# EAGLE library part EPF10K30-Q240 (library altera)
EPF10K30 FLEX 10K family
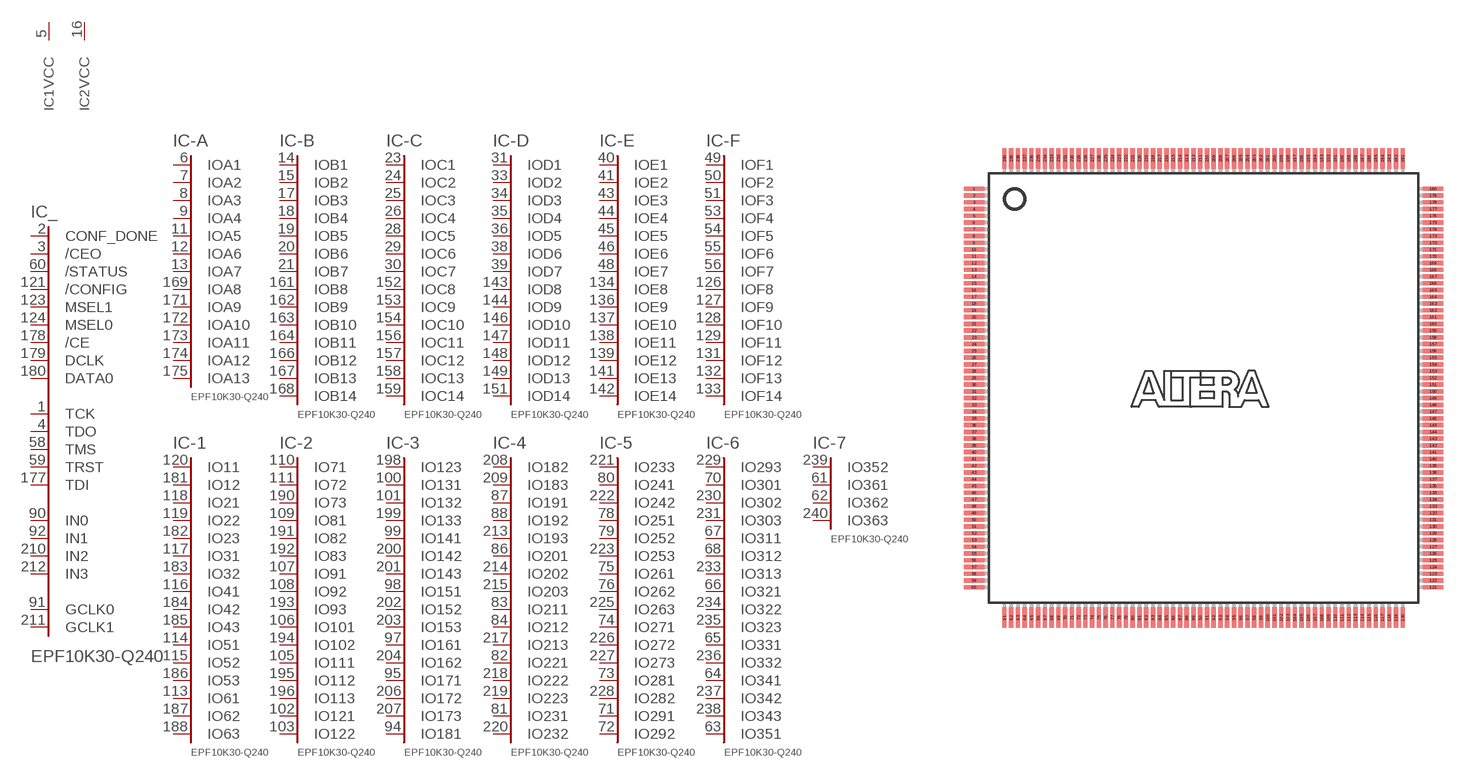
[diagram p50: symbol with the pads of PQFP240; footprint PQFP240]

Designator prefix IC; gates _=100R240C -A=A13 -B=B14 -C=C14 -D=D14 -E=E14 -F=F14 -1=63-K30Q -2=122-K30Q -3=181-K30Q -4=232-K30Q -5=292-K30Q -6=351-K30Q -7=363-K30Q 1=VCCINT 2=VCCINT 3=VCCINT 4=VCCINT 5=VCCINT 6=VCCINT 7=VCCINT 8=VCCINT 9=VCCINT 10=VCCINT 11=VCCINT 12=VCCINT 13=VCCINT 14=VCCINT 15=VCCINT 16=VCCINT 17=VCCINT 18=VCCINT 19=VCCINT 20=GNDINT 21=GNDINT 22=GNDINT 23=GNDINT 24=GNDINT 25=GNDINT 26=GNDINT 27=GNDINT 28=GNDINT 29=GNDINT 30=GNDINT 31=GNDINT 32=GNDINT 33=GNDINT 34=GNDINT 35=GNDINT 36=GNDINT 37=GNDINT

## EPF10K30-Q240 (MPN: EPF10K30AQC240-3N; OC_FARNELL: 1549384; OC_NEWARK: 51R8956)  [PQFP240]
1  _:TCK
2  _:CONF_DONE  in
3  _:/CEO  in
4  _:TDO
5  1:VCC  pwr
6  -A:IOA1
7  -A:IOA2
8  -A:IOA3
9  -A:IOA4
10  20:GND  pwr
11  -A:IOA5
12  -A:IOA6
13  -A:IOA7
14  -B:IOB1
15  -B:IOB2
16  2:VCC  pwr
17  -B:IOB3
18  -B:IOB4
19  -B:IOB5
20  -B:IOB6
21  -B:IOB7
22  21:GND  pwr
23  -C:IOC1
24  -C:IOC2
25  -C:IOC3
26  -C:IOC4
27  3:VCC  pwr
28  -C:IOC5
29  -C:IOC6
30  -C:IOC7
31  -D:IOD1
32  22:GND  pwr
33  -D:IOD2
34  -D:IOD3
35  -D:IOD4
36  -D:IOD5
37  4:VCC  pwr
38  -D:IOD6
39  -D:IOD7
40  -E:IOE1
41  -E:IOE2
42  23:GND  pwr
43  -E:IOE3
44  -E:IOE4
45  -E:IOE5
46  -E:IOE6
47  5:VCC  pwr
48  -E:IOE7
49  -F:IOF1
50  -F:IOF2
51  -F:IOF3
52  24:GND  pwr
53  -F:IOF4
54  -F:IOF5
55  -F:IOF6
56  -F:IOF7
57  6:VCC  pwr
58  _:TMS
59  _:TRST
60  _:/STATUS  in
61  -7:IO361
62  -7:IO362
63  -6:IO351
64  -6:IO341
65  -6:IO331
66  -6:IO321
67  -6:IO311
68  -6:IO312
69  25:GND  pwr
70  -6:IO301
71  -5:IO291
72  -5:IO292
73  -5:IO281
74  -5:IO271
75  -5:IO261
76  -5:IO262
77  7:VCC  pwr
78  -5:IO251
79  -5:IO252
80  -5:IO241
81  -4:IO231
82  -4:IO221
83  -4:IO211
84  -4:IO212
85  26:GND  pwr
86  -4:IO201
87  -4:IO191
88  -4:IO192
89  8:VCC  pwr
90  _:IN0  in
91  _:GCLK0  in
92  _:IN1  in
93  27:GND  pwr
94  -3:IO181
95  -3:IO171
96  9:VCC  pwr
97  -3:IO161
98  -3:IO151
99  -3:IO141
100  -3:IO131
101  -3:IO132
102  -2:IO121
103  -2:IO122
104  28:GND  pwr
105  -2:IO111
106  -2:IO101
107  -2:IO91
108  -2:IO92
109  -2:IO81
110  -2:IO71
111  -2:IO72
112  10:VCC  pwr
113  -1:IO61
114  -1:IO51
115  -1:IO52
116  -1:IO41
117  -1:IO31
118  -1:IO21
119  -1:IO22
120  -1:IO11
121  _:/CONFIG  in
122  11:VCC  pwr
123  _:MSEL1  in
124  _:MSEL0  in
125  29:GND  pwr
126  -F:IOF8
127  -F:IOF9
128  -F:IOF10
129  -F:IOF11
130  12:VCC  pwr
131  -F:IOF12
132  -F:IOF13
133  -F:IOF14
134  -E:IOE8
135  30:GND  pwr
136  -E:IOE9
137  -E:IOE10
138  -E:IOE11
139  -E:IOE12
140  13:VCC  pwr
141  -E:IOE13
142  -E:IOE14
143  -D:IOD8
144  -D:IOD9
145  31:GND  pwr
146  -D:IOD10
147  -D:IOD11
148  -D:IOD12
149  -D:IOD13
150  14:VCC  pwr
151  -D:IOD14
152  -C:IOC8
153  -C:IOC9
154  -C:IOC10
155  32:GND  pwr
156  -C:IOC11
157  -C:IOC12
158  -C:IOC13
159  -C:IOC14
160  15:VCC  pwr
161  -B:IOB8
162  -B:IOB9
163  -B:IOB10
164  -B:IOB11
165  33:GND  pwr
166  -B:IOB12
167  -B:IOB13
168  -B:IOB14
169  -A:IOA8
170  16:VCC  pwr
171  -A:IOA9
172  -A:IOA10
173  -A:IOA11
174  -A:IOA12
175  -A:IOA13
176  34:GND  pwr
177  _:TDI
178  _:/CE  in
179  _:DCLK  in
180  _:DATA0  in
181  -1:IO12
182  -1:IO23
183  -1:IO32
184  -1:IO42
185  -1:IO43
186  -1:IO53
187  -1:IO62
188  -1:IO63
189  17:VCC  pwr
190  -2:IO73
191  -2:IO82
192  -2:IO83
193  -2:IO93
194  -2:IO102
195  -2:IO112
196  -2:IO113
197  35:GND  pwr
198  -3:IO123
199  -3:IO133
200  -3:IO142
201  -3:IO143
202  -3:IO152
203  -3:IO153
204  -3:IO162
205  18:VCC  pwr
206  -3:IO172
207  -3:IO173
208  -4:IO182
209  -4:IO183
210  _:IN2  in
211  _:GCLK1  in
212  _:IN3  in
213  -4:IO193
214  -4:IO202
215  -4:IO203
216  36:GND  pwr
217  -4:IO213
218  -4:IO222
219  -4:IO223
220  -4:IO232
221  -5:IO233
222  -5:IO242
223  -5:IO253
224  19:VCC  pwr
225  -5:IO263
226  -5:IO272
227  -5:IO273
228  -5:IO282
229  -6:IO293
230  -6:IO302
231  -6:IO303
232  37:GND  pwr
233  -6:IO313
234  -6:IO322
235  -6:IO323
236  -6:IO332
237  -6:IO342
238  -6:IO343
239  -7:IO352
240  -7:IO363

## Footprint PQFP240 (pad centres in mm)
Plastic Quad Flat Pack
smd 1.5 x 0.32: 1 -17,14.75; 2 -17,14.25; 3 -17,13.75; 4 -17,13.25; 5 -17,12.75; 6 -17,12.25; 7 -17,11.75; 8 -17,11.25; 9 -17,10.75; 10 -17,10.25; 11 -17,9.75; 12 -17,9.25; 13 -17,8.75; 14 -17,8.25; 15 -17,7.75; 16 -17,7.25; 17 -17,6.75; 18 -17,6.25; 19 -17,5.75; 20 -17,5.25; 21 -17,4.75; 22 -17,4.25; 23 -17,3.75; 24 -17,3.25; 25 -17,2.75; 26 -17,2.25; 27 -17,1.75; 28 -17,1.25; 29 -17,0.75; 30 -17,0.25; 31 -17,-0.25; 32 -17,-0.75; 33 -17,-1.25; 34 -17,-1.75; 35 -17,-2.25; 36 -17,-2.75; 37 -17,-3.25; 38 -17,-3.75; 39 -17,-4.25; 40 -17,-4.75; 41 -17,-5.25; 42 -17,-5.75; 43 -17,-6.25; 44 -17,-6.75; 45 -17,-7.25; 46 -17,-7.75; 47 -17,-8.25; 48 -17,-8.75; 49 -17,-9.25; 50 -17,-9.75; 51 -17,-10.25; 52 -17,-10.75; 53 -17,-11.25; 54 -17,-11.75; 55 -17,-12.25; 56 -17,-12.75; 57 -17,-13.25; 58 -17,-13.75; 59 -17,-14.25; 60 -17,-14.75; 121 17,-14.75; 122 17,-14.25; 123 17,-13.75; 124 17,-13.25; 125 17,-12.75; 126 17,-12.25; 127 17,-11.75; 128 17,-11.25; 129 17,-10.75; 130 17,-10.25; 131 17,-9.75; 132 17,-9.25; 133 17,-8.75; 134 17,-8.25; 135 17,-7.75; 136 17,-7.25; 137 17,-6.75; 138 17,-6.25; 139 17,-5.75; 140 17,-5.25; 141 17,-4.75; 142 17,-4.25; 143 17,-3.75; 144 17,-3.25; 145 17,-2.75; 146 17,-2.25; 147 17,-1.75; 148 17,-1.25; 149 17,-0.75; 150 17,-0.25; 151 17,0.25; 152 17,0.75; 153 17,1.25; 154 17,1.75; 155 17,2.25; 156 17,2.75; 157 17,3.25; 158 17,3.75; 159 17,4.25; 160 17,4.75; 161 17,5.25; 162 17,5.75; 163 17,6.25; 164 17,6.75; 165 17,7.25; 166 17,7.75; 167 17,8.25; 168 17,8.75; 169 17,9.25; 170 17,9.75; 171 17,10.25; 172 17,10.75; 173 17,11.25; 174 17,11.75; 175 17,12.25; 176 17,12.75; 177 17,13.25; 178 17,13.75; 179 17,14.25; 180 17,14.75
smd 0.32 x 1.5: 61 -14.75,-17; 62 -14.25,-17; 63 -13.75,-17; 64 -13.25,-17; 65 -12.75,-17; 66 -12.25,-17; 67 -11.75,-17; 68 -11.25,-17; 69 -10.75,-17; 70 -10.25,-17; 71 -9.75,-17; 72 -9.25,-17; 73 -8.75,-17; 74 -8.25,-17; 75 -7.75,-17; 76 -7.25,-17; 77 -6.75,-17; 78 -6.25,-17; 79 -5.75,-17; 80 -5.25,-17; 81 -4.75,-17; 82 -4.25,-17; 83 -3.75,-17; 84 -3.25,-17; 85 -2.75,-17; 86 -2.25,-17; 87 -1.75,-17; 88 -1.25,-17; 89 -0.75,-17; 90 -0.25,-17; 91 0.25,-17; 92 0.75,-17; 93 1.25,-17; 94 1.75,-17; 95 2.25,-17; 96 2.75,-17; 97 3.25,-17; 98 3.75,-17; 99 4.25,-17; 100 4.75,-17; 101 5.25,-17; 102 5.75,-17; 103 6.25,-17; 104 6.75,-17; 105 7.25,-17; 106 7.75,-17; 107 8.25,-17; 108 8.75,-17; 109 9.25,-17; 110 9.75,-17; 111 10.25,-17; 112 10.75,-17; 113 11.25,-17; 114 11.75,-17; 115 12.25,-17; 116 12.75,-17; 117 13.25,-17; 118 13.75,-17; 119 14.25,-17; 120 14.75,-17; 181 14.75,17; 182 14.25,17; 183 13.75,17; 184 13.25,17; 185 12.75,17; 186 12.25,17; 187 11.75,17; 188 11.25,17; 189 10.75,17; 190 10.25,17; 191 9.75,17; 192 9.25,17; 193 8.75,17; 194 8.25,17; 195 7.75,17; 196 7.25,17; 197 6.75,17; 198 6.25,17; 199 5.75,17; 200 5.25,17; 201 4.75,17; 202 4.25,17; 203 3.75,17; 204 3.25,17; 205 2.75,17; 206 2.25,17; 207 1.75,17; 208 1.25,17; 209 0.75,17; 210 0.25,17; 211 -0.25,17; 212 -0.75,17; 213 -1.25,17; 214 -1.75,17; 215 -2.25,17; 216 -2.75,17; 217 -3.25,17; 218 -3.75,17; 219 -4.25,17; 220 -4.75,17; 221 -5.25,17; 222 -5.75,17; 223 -6.25,17; 224 -6.75,17; 225 -7.25,17; 226 -7.75,17; 227 -8.25,17; 228 -8.75,17; 229 -9.25,17; 230 -9.75,17; 231 -10.25,17; 232 -10.75,17; 233 -11.25,17; 234 -11.75,17; 235 -12.25,17; 236 -12.75,17; 237 -13.25,17; 238 -13.75,17; 239 -14.25,17; 240 -14.75,17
